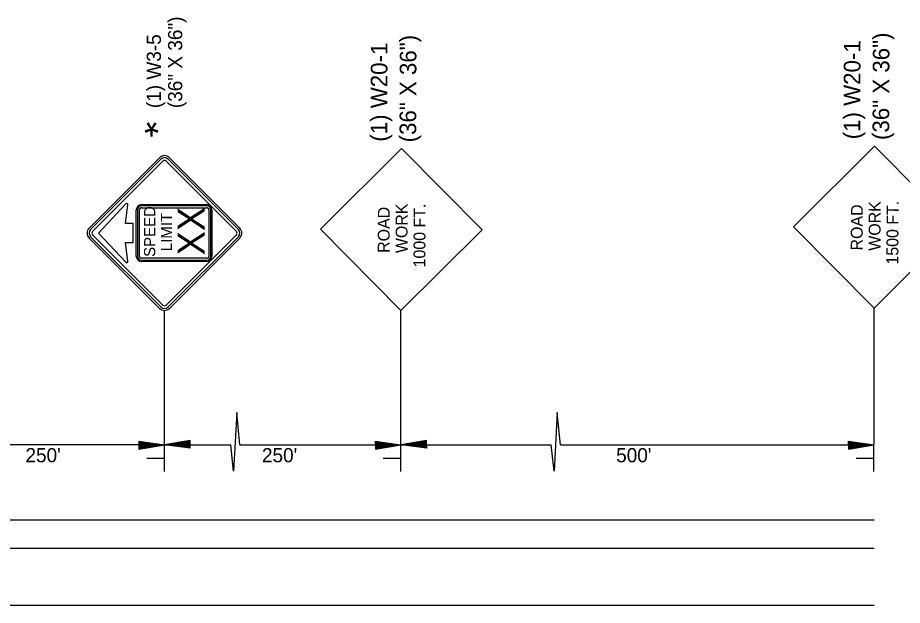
# Model space of a CAD drawing. Extents: x -160 to 6143532, y -375 to 762199.
# Drawn here: x -54.93 to -21.54, y 75.62 to 97.78 of the extents above; entities that cross this region are included whole.
import ezdxf

# ---------------------------------------------------------------- set-up
doc = ezdxf.new("R2010")
doc.units = 0
for name, color, linetype in [('Level 3', 7, 'Continuous'), ('Level 8', 7, 'Continuous'), ('P_TC_Signs_Permanent', 7, 'Continuous'), ('R_Annotation', 7, 'Continuous'), ('R_Centerline', 7, 'Continuous'), ('R_Dimension', 7, 'Continuous'), ('R_Draft', 7, 'Continuous')]:
    doc.layers.add(name, color=color, linetype=linetype)

msp = doc.modelspace()

# ---------------------------------------------------------------- linework, layer by layer
at = {"layer": 'Level 3'}
for p, q in [((-49.388, 80.67), (-49.388, 81.634)), ((-40.462, 80.67), (-40.462, 81.634)), ((-22.61, 80.67), (-22.61, 81.634)), ((-49.402, 81.15), (-50.06, 81.15)), ((-40.476, 81.15), (-41.134, 81.15)), ((-22.624, 81.15), (-23.282, 81.15))]:
    msp.add_line(p, q, dxfattribs=at)
at = {"layer": 'Level 8'}
for p, q in [((-40.444, 92.841), (-43.504, 89.799)), ((-40.444, 92.841), (-37.404, 89.781)), ((-22.591, 92.931), (-25.651, 89.889)), ((-22.591, 92.931), (-19.552, 89.871)), ((-25.651, 89.889), (-22.609, 86.829)), ((-19.552, 89.871), (-22.609, 86.829)), ((-43.504, 89.799), (-40.462, 86.739)), ((-37.404, 89.781), (-40.462, 86.739))]:
    msp.add_line(p, q, dxfattribs=at)
at = {"layer": 'P_TC_Signs_Permanent'}
for p, q in [((-49.577, 92.498), (-52.228, 89.847)), ((-46.547, 89.847), (-49.198, 92.498)), ((-49.525, 92.446), (-52.175, 89.795)), ((-49.451, 92.372), (-52.102, 89.721)), ((-46.674, 89.721), (-49.325, 92.372)), ((-46.6, 89.795), (-49.251, 92.446)), ((-50.451, 88.777), (-50.451, 90.539)), ((-50.261, 90.729), (-47.786, 90.729)), ((-47.595, 90.539), (-47.595, 88.777)), ((-52.175, 89.521), (-49.525, 86.87)), ((-52.102, 89.595), (-49.451, 86.944)), ((-49.325, 86.944), (-46.674, 89.595)), ((-49.251, 86.87), (-46.6, 89.521)), ((-52.228, 89.469), (-49.577, 86.818)), ((-49.198, 86.818), (-46.547, 89.469)), ((-47.786, 88.587), (-50.261, 88.587))]:
    msp.add_line(p, q, dxfattribs=at)
for points in [[(-50.841, 90.756), (-51.88, 89.655), (-50.841, 88.554)], [(-50.765, 88.59), (-50.854, 89.301), (-50.571, 89.301), (-50.571, 90.015), (-50.853, 90.015), (-50.765, 90.72)], [(-50.404, 90.539), (-50.404, 89.658), (-50.404, 88.777)], [(-50.332, 88.777), (-50.332, 89.658), (-50.332, 90.539)], [(-47.786, 90.681), (-50.261, 90.681)], [(-50.261, 90.61), (-47.786, 90.61)], [(-47.714, 90.539), (-47.714, 88.777)], [(-47.643, 88.777), (-47.643, 90.539)], [(-47.786, 88.706), (-50.261, 88.706)], [(-50.261, 88.634), (-47.786, 88.634)]]:
    msp.add_lwpolyline(points, dxfattribs=at)
for centre, radius, start, end in [((-49.388, 92.309), 0.268, 45, 135), ((-49.388, 92.309), 0.193, 45, 135), ((-49.388, 92.309), 0.0893, 45, 135), ((-50.809, 90.726), 0.0446, 352.875, 136.6883), ((-50.261, 90.539), 0.19, 90, 180), ((-50.261, 90.539), 0.143, 90, 180), ((-50.261, 90.539), 0.0714, 90, 180), ((-47.786, 90.539), 0.19, 0, 90), ((-47.786, 90.539), 0.143, 0, 90), ((-47.786, 90.539), 0.0714, 0, 90), ((-52.039, 89.658), 0.268, 135, 225), ((-46.737, 89.658), 0.268, 315, 45), ((-52.039, 89.658), 0.193, 135, 225), ((-52.039, 89.658), 0.0893, 135, 225), ((-46.737, 89.658), 0.0893, 315, 45), ((-46.737, 89.658), 0.193, 315, 45), ((-50.809, 88.584), 0.0446, 223.3117, 7.125), ((-50.261, 88.777), 0.19, 180, 270), ((-50.261, 88.777), 0.143, 180, 270), ((-50.261, 88.777), 0.0714, 180, 270), ((-47.786, 88.777), 0.19, 270, 0), ((-47.786, 88.777), 0.143, 270, 0), ((-47.786, 88.777), 0.0714, 270, 0), ((-49.388, 87.007), 0.268, 225, 315), ((-49.388, 87.007), 0.193, 225, 315), ((-49.388, 87.007), 0.0893, 225, 315)]:
    msp.add_arc(centre, radius, start, end, dxfattribs=at)
at = {"layer": 'R_Centerline'}
msp.add_line((-83.854, 75.619), (-22.609, 75.619), dxfattribs=at)
at = {"layer": 'R_Dimension'}
for p, q in [((-22.609, 81.674), (-22.609, 86.829)), ((-49.388, 81.674), (-49.388, 86.739)), ((-40.462, 81.674), (-40.462, 86.739)), ((-50.361, 81.804), (-49.388, 81.674)), ((-50.361, 81.804), (-50.357, 81.513)), ((-50.361, 81.804), (-49.388, 81.674)), ((-50.361, 81.804), (-50.357, 81.513)), ((-48.419, 81.836), (-49.388, 81.674)), ((-48.419, 81.812), (-49.225, 81.677)), ((-48.414, 81.544), (-48.419, 81.836)), ((-41.435, 81.804), (-40.462, 81.674)), ((-41.435, 81.804), (-41.43, 81.513)), ((-39.493, 81.836), (-40.462, 81.674)), ((-39.492, 81.812), (-40.299, 81.677)), ((-39.488, 81.544), (-39.493, 81.836)), ((-23.582, 81.804), (-22.609, 81.674)), ((-23.582, 81.804), (-23.578, 81.513)), ((-49.388, 81.674), (-55.727, 81.674)), ((-50.361, 81.78), (-49.55, 81.672)), ((-50.361, 81.78), (-49.55, 81.672)), ((-50.36, 81.755), (-49.717, 81.669)), ((-50.36, 81.755), (-49.717, 81.669)), ((-50.36, 81.731), (-49.879, 81.666)), ((-50.36, 81.731), (-49.879, 81.666)), ((-50.359, 81.706), (-50.043, 81.664)), ((-50.359, 81.706), (-50.043, 81.664)), ((-50.359, 81.682), (-50.206, 81.661)), ((-50.359, 81.682), (-50.205, 81.661)), ((-50.359, 81.636), (-50.206, 81.661)), ((-50.359, 81.636), (-50.205, 81.661)), ((-50.358, 81.587), (-49.879, 81.666)), ((-50.358, 81.586), (-49.879, 81.666)), ((-50.358, 81.611), (-50.043, 81.664)), ((-50.358, 81.611), (-50.043, 81.664)), ((-50.357, 81.513), (-49.388, 81.674)), ((-50.357, 81.513), (-49.388, 81.674)), ((-50.357, 81.538), (-49.55, 81.672)), ((-50.357, 81.537), (-49.55, 81.672)), ((-50.357, 81.562), (-49.717, 81.669)), ((-50.357, 81.562), (-49.717, 81.669)), ((-49.388, 81.674), (-46.888, 81.674)), ((-48.414, 81.544), (-49.388, 81.674)), ((-48.415, 81.569), (-49.225, 81.677)), ((-48.418, 81.786), (-49.059, 81.68)), ((-48.415, 81.593), (-49.059, 81.68)), ((-48.418, 81.763), (-48.897, 81.682)), ((-48.416, 81.618), (-48.897, 81.682)), ((-48.417, 81.737), (-48.732, 81.685)), ((-48.416, 81.643), (-48.732, 81.685)), ((-48.417, 81.713), (-48.57, 81.688)), ((-48.416, 81.667), (-48.57, 81.688)), ((-46.541, 81.674), (-40.462, 81.674)), ((-41.434, 81.78), (-40.624, 81.672)), ((-41.434, 81.755), (-40.791, 81.669)), ((-41.434, 81.731), (-40.952, 81.666)), ((-41.433, 81.706), (-41.117, 81.664)), ((-41.433, 81.682), (-41.279, 81.661)), ((-41.432, 81.587), (-40.952, 81.666)), ((-41.432, 81.611), (-41.117, 81.664)), ((-41.432, 81.636), (-41.279, 81.661)), ((-41.431, 81.538), (-40.624, 81.672)), ((-41.431, 81.562), (-40.791, 81.669)), ((-41.43, 81.513), (-40.462, 81.674)), ((-40.462, 81.674), (-34.791, 81.674)), ((-39.488, 81.544), (-40.462, 81.674)), ((-39.489, 81.569), (-40.299, 81.677)), ((-39.492, 81.786), (-40.133, 81.68)), ((-39.489, 81.593), (-40.133, 81.68)), ((-39.491, 81.763), (-39.971, 81.682)), ((-39.489, 81.618), (-39.971, 81.682)), ((-39.491, 81.737), (-39.806, 81.685)), ((-39.49, 81.643), (-39.806, 81.685)), ((-39.491, 81.713), (-39.644, 81.688)), ((-39.49, 81.667), (-39.644, 81.688)), ((-34.444, 81.674), (-22.609, 81.674)), ((-23.582, 81.78), (-22.771, 81.672)), ((-23.582, 81.755), (-22.938, 81.669)), ((-23.581, 81.731), (-23.1, 81.666)), ((-23.581, 81.706), (-23.265, 81.664)), ((-23.581, 81.682), (-23.427, 81.661)), ((-23.58, 81.611), (-23.265, 81.664)), ((-23.58, 81.636), (-23.427, 81.661)), ((-23.579, 81.562), (-22.938, 81.669)), ((-23.579, 81.587), (-23.1, 81.666)), ((-23.578, 81.513), (-22.609, 81.674)), ((-23.578, 81.538), (-22.771, 81.672))]:
    msp.add_line(p, q, dxfattribs=at)
for points in [[(-46.541, 81.674), (-46.658, 82.893), (-46.78, 80.681)], [(-34.444, 81.674), (-34.562, 82.893), (-34.683, 80.681)], [(-46.78, 80.681), (-46.888, 81.674)], [(-34.683, 80.681), (-34.791, 81.674)]]:
    msp.add_lwpolyline(points, dxfattribs=at)
at = {"layer": 'R_Draft'}
for p, q in [((-22.609, 78.824), (-83.854, 78.824)), ((-22.609, 77.756), (-83.854, 77.756))]:
    msp.add_line(p, q, dxfattribs=at)

# ---------------------------------------------------------------- texts
at = {"layer": 'Level 8'}
for s, height, rotation, p in [('(36" X 36")', 0.62813, 89.8307, (-22.037, 93.166)), ('(36" X 36")', 0.62813, 89.8307, (-39.889, 93.077)), ('(1) W20-1', 0.6281, 89.8307, (-23.13, 93.193)), ('(1) W20-1', 0.6281, 89.8307, (-40.982, 93.103)), ('WORK', 0.4494, 89.8307, (-22.363, 88.989)), ('1500 FT.', 0.4495, 89.8313, (-21.691, 88.468)), ('SPEED ', 0.4224, 90, (-49.736, 88.758)), ('XX', 1.0233, 90, (-47.872, 88.818)), ('ROAD', 0.4495, 89.8312, (-40.89, 88.91)), ('WORK', 0.4494, 89.8307, (-40.216, 88.899)), ('1000 FT.', 0.4495, 89.8313, (-39.543, 88.361)), ('ROAD', 0.4495, 89.8312, (-23.037, 89)), ('LIMIT', 0.4224, 90, (-49.103, 88.974))]:
    msp.add_text(s, height=height, rotation=rotation, dxfattribs=at).set_placement(p)
at = {"layer": 'R_Annotation'}
for s, height, rotation, p in [('(36" X 36")', 0.53557, 90, (-48.718, 94.369)), ('(1) W3-5', 0.5356, 90, (-49.522, 94.369)), ('*', 1.071, 180, (-49.598, 94.359)), ("250'", 0.5356, 360, (-54.635, 81.012)), ("250'", 0.5356, 360, (-45.709, 81.012)), ("500'", 0.5356, 360, (-32.341, 81.012))]:
    msp.add_text(s, height=height, rotation=rotation, dxfattribs=at).set_placement(p)

doc.saveas('drawing.dxf')
